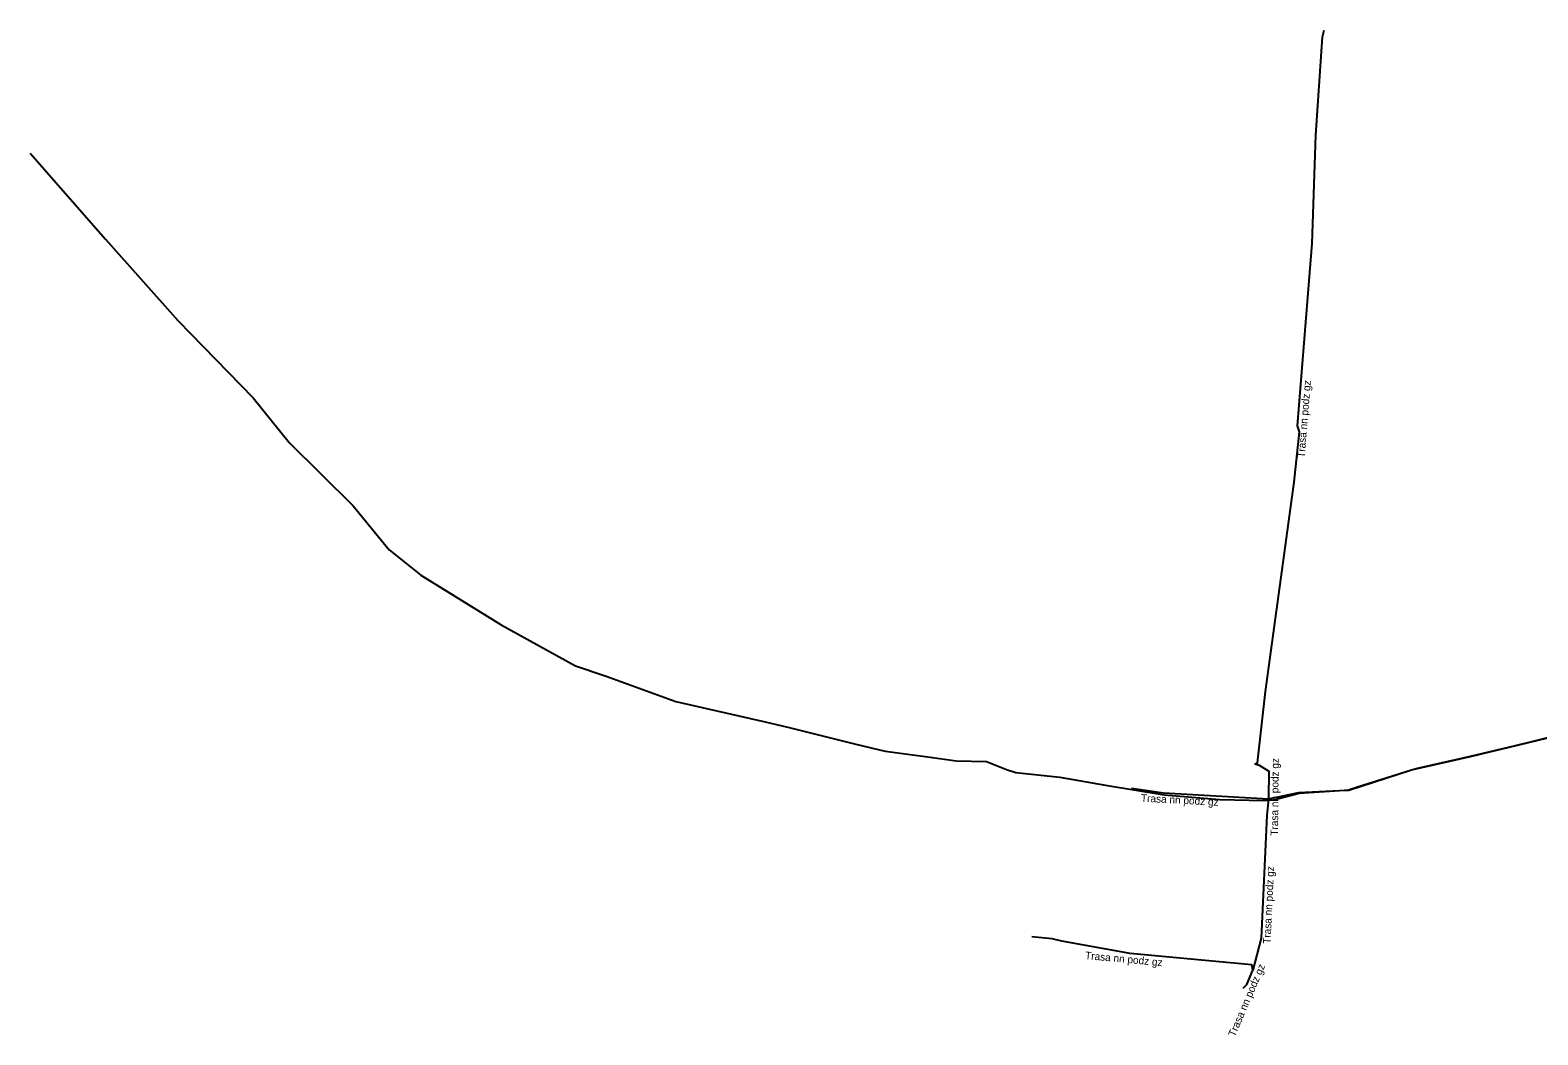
# Model space of a CAD drawing. Extents: x -687924 to -686708, y -1056742 to -1056249.
# Drawn here: x -687924.4 to -687824.2, y -1056686.2 to -1056619.4 of the extents above; entities that cross this region are included whole.
import ezdxf

# ---------------------------------------------------------------- set-up
doc = ezdxf.new("R2010")
doc.units = 0
for name, color, linetype in [('Popiskový text - Ostatní atributy Trasy', 7, 'Continuous'), ('Spojnice NN', 7, 'Continuous'), ('Spojnice VN', 7, 'Continuous')]:
    doc.layers.add(name, color=color, linetype=linetype)

msp = doc.modelspace()

# ---------------------------------------------------------------- linework, layer by layer
at = {"layer": 'Spojnice NN'}
for points in [[(-687842.97, -1056668.16), (-687842.81, -1056668.09), (-687842.27, -1056663.35), (-687840.37, -1056649.42), (-687840.02, -1056646.07), (-687840.15, -1056645.69), (-687839.16, -1056633.55), (-687838.93, -1056626.34), (-687838.49, -1056619.81), (-687838.37, -1056619.36)], [(-687842.07, -1056670.49), (-687840.06, -1056670.06), (-687837.35, -1056669.94), (-687836.75, -1056669.89), (-687836.22, -1056669.72), (-687832.57, -1056668.56), (-687832.25, -1056668.48), (-687828.65, -1056667.65), (-687825.66, -1056666.94), (-687822.85, -1056666.26), (-687819.01, -1056665.42), (-687813.09, -1056664.12), (-687809.94, -1056663.47), (-687804.77, -1056662.22), (-687799.38, -1056661.1), (-687798.84, -1056660.96), (-687794.7, -1056659.66)], [(-687842.97, -1056668.16), (-687842.7, -1056668.25), (-687842.05, -1056668.65), (-687842.07, -1056670.49)], [(-687851.19, -1056669.78), (-687849.06, -1056670.1), (-687842.07, -1056670.49)], [(-687842.07, -1056670.49), (-687842.19, -1056671.6), (-687842.57, -1056679.76), (-687843.11, -1056681.88)], [(-687843.11, -1056681.88), (-687843.17, -1056681.54), (-687845.58, -1056681.3), (-687851.26, -1056680.77), (-687855.82, -1056679.96), (-687856.45, -1056679.79), (-687857.8, -1056679.67)], [(-687843.75, -1056683.08), (-687843.52, -1056682.83), (-687843.11, -1056681.88)]]:
    msp.add_lwpolyline(points, dxfattribs=at)
at = {"layer": 'Spojnice VN'}
msp.add_lwpolyline([(-687924.39, -1056627.55), (-687919.38, -1056633.26), (-687914.56, -1056638.69), (-687909.57, -1056643.82), (-687907.18, -1056646.79), (-687902.92, -1056651.01), (-687900.52, -1056653.92), (-687898.43, -1056655.62), (-687896.63, -1056656.72), (-687893.08, -1056658.91), (-687888.13, -1056661.64), (-687886.11, -1056662.33), (-687881.46, -1056664.01), (-687875.53, -1056665.37), (-687874.03, -1056665.73), (-687869.5, -1056666.86), (-687867.55, -1056667.32), (-687864.72, -1056667.69), (-687862.84, -1056667.95), (-687860.82, -1056668.01), (-687859.49, -1056668.53), (-687858.86, -1056668.74), (-687855.95, -1056669.04), (-687852.91, -1056669.59), (-687849.01, -1056670.22), (-687845.3, -1056670.54), (-687842.38, -1056670.61), (-687841.72, -1056670.56), (-687840.04, -1056670.11), (-687837.35, -1056669.94), (-687836.74, -1056669.91), (-687832.57, -1056668.57), (-687828.65, -1056667.68), (-687822.85, -1056666.28)], dxfattribs=at)

# ---------------------------------------------------------------- texts
at = {"layer": 'Popiskový text - Ostatní atributy Trasy'}
for rotation, p in [(85.3726, (-687839.67, -1056647.82)), (89.4709, (-687841.44, -1056672.94)), (356.8174, (-687850.56, -1056670.67)), (87.28, (-687841.94, -1056680.14)), (354.6045, (-687854.28, -1056681.14)), (66.8671, (-687844.31, -1056686.35))]:
    msp.add_text('Trasa nn podz gz', height=0.5, rotation=rotation, dxfattribs=at).set_placement(p)

doc.saveas('drawing.dxf')
